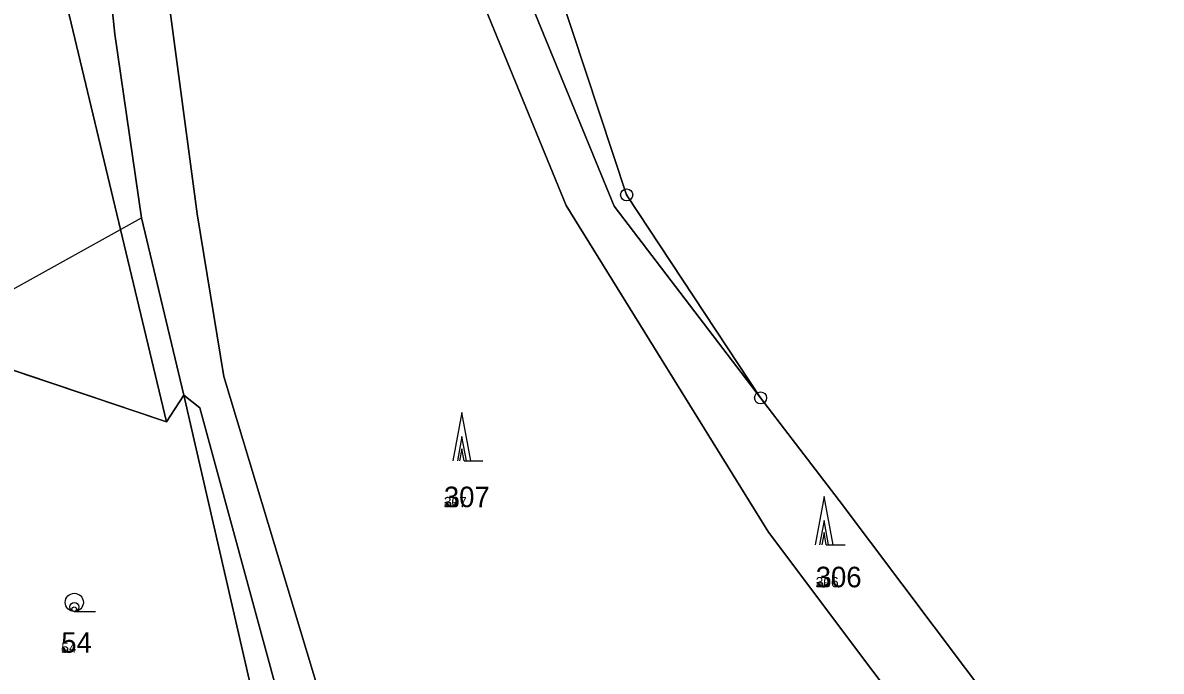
# Model space of a CAD drawing. Extents: x -759873 to -758487, y -975024 to -973516.
# Drawn here: x -759094.4 to -759000.3, y -974260.8 to -974207.1 of the extents above; entities that cross this region are included whole.
import ezdxf

# ---------------------------------------------------------------- set-up
doc = ezdxf.new("R2010")
doc.units = 0
for name, color, linetype in [('KAT_02_hranice parcel', 7, 'Continuous'), ('KAT_03_1000_čísla parcelní', 7, 'Continuous'), ('KAT_03_250_čísla parcelní', 7, 'Continuous'), ('KAT_03_500_čísla parcelní', 7, 'Continuous'), ('KAT_04_vnitřní kresba', 7, 'Continuous'), ('KAT_05_1000_značky kultur', 7, 'Continuous'), ('KAT_05_250_značky kultur', 7, 'Continuous'), ('KAT_05_500_značky kultur', 7, 'Continuous'), ('KAT_11_značky bodu BP', 7, 'Continuous'), ('KAT_14_plocha_pozemek', 7, 'Continuous')]:
    doc.layers.add(name, color=color, linetype=linetype)

msp = doc.modelspace()

# ---------------------------------------------------------------- linework, layer by layer
at = {"layer": 'KAT_02_hranice parcel'}
for p, q in [((-759082.54, -974240.13), (-759102.76, -974233.33)), ((-759081.12, -974237.92), (-759082.54, -974240.13)), ((-759072.72, -974274.42), (-759081.12, -974237.92))]:
    msp.add_line(p, q, dxfattribs=at)
for points in [[(-759057.23, -974110.82), (-759070.93, -974124.94), (-759074.88, -974130.5), (-759080.81, -974167.04), (-759083.49, -974196.85), (-759080.01, -974222.92), (-759077.81, -974236.38), (-759067.25, -974271.4), (-759032.56, -974317.79)], [(-759057.23, -974110.82), (-759060.75, -974132.98), (-759061.42, -974162.34), (-759060.12, -974196.25), (-759049.48, -974222.24), (-759032.75, -974249.27), (-759006.93, -974283.66), (-759017.69, -974290.39), (-759014.33, -974293.41)], [(-759082.54, -974240.13), (-759086.34, -974224.22), (-759091.94, -974200.78), (-759089.9, -974172.96), (-759085.8, -974168.68)], [(-759081.12, -974237.92), (-759084.6, -974223.26), (-759086.81, -974208.04), (-759088.06, -974196.14), (-759087.54, -974184.43), (-759085.8, -974168.68)], [(-759033.4, -974238.15), (-759044.48, -974221.35), (-759056.91, -974183.77)], [(-759056.91, -974183.77), (-759056.12, -974196.39), (-759045.51, -974222.29), (-759033.4, -974238.15)], [(-759081.12, -974237.92), (-759079.79, -974238.96), (-759070.66, -974272.52)], [(-759033.4, -974238.15), (-759026.91, -974246.64), (-759000.81, -974281.35), (-758999.72, -974284.7), (-759014.33, -974293.41)]]:
    msp.add_lwpolyline(points, dxfattribs=at)
at = {"layer": 'KAT_04_vnitřní kresba'}
for p, q in [((-759086.34, -974224.22), (-759084.6, -974223.26)), ((-759102.76, -974233.33), (-759086.34, -974224.22))]:
    msp.add_line(p, q, dxfattribs=at)
at = {"layer": 'KAT_05_1000_značky kultur'}
for p, q in [((-759058.11, -974239.35), (-759058.86, -974243.35)), ((-759057.36, -974243.35), (-759058.11, -974239.35)), ((-759057.36, -974243.35), (-759056.364, -974243.35)), ((-759028.15, -974246.3), (-759028.9, -974250.3)), ((-759027.4, -974250.3), (-759028.15, -974246.3)), ((-759027.4, -974250.3), (-759026.404, -974250.3)), ((-759090.173, -974255.82), (-759088.423, -974255.82))]:
    msp.add_line(p, q, dxfattribs=at)
msp.add_circle((-759090.173, -974255.07), 0.75, dxfattribs=at)
at = {"layer": 'KAT_05_250_značky kultur'}
for p, q in [((-759058.11, -974242.35), (-759058.297, -974243.35)), ((-759057.922, -974243.35), (-759058.11, -974242.35)), ((-759057.922, -974243.35), (-759057.674, -974243.35)), ((-759028.15, -974249.3), (-759028.338, -974250.3)), ((-759027.963, -974250.3), (-759028.15, -974249.3)), ((-759027.963, -974250.3), (-759027.714, -974250.3)), ((-759090.178, -974255.82), (-759089.741, -974255.82))]:
    msp.add_line(p, q, dxfattribs=at)
msp.add_circle((-759090.178, -974255.632), 0.187, dxfattribs=at)
at = {"layer": 'KAT_05_500_značky kultur'}
for p, q in [((-759058.11, -974241.35), (-759058.485, -974243.35)), ((-759057.735, -974243.35), (-759058.11, -974241.35)), ((-759057.735, -974243.35), (-759057.237, -974243.35)), ((-759028.15, -974248.3), (-759028.525, -974250.3)), ((-759027.775, -974250.3), (-759028.15, -974248.3)), ((-759027.775, -974250.3), (-759027.277, -974250.3)), ((-759090.177, -974255.82), (-759089.302, -974255.82))]:
    msp.add_line(p, q, dxfattribs=at)
msp.add_circle((-759090.176, -974255.445), 0.375, dxfattribs=at)
at = {"layer": 'KAT_11_značky bodu BP'}
for centre, radius in [((-759044.48, -974221.35), 0.5), ((-759044.48, -974221.35), 0.0303), ((-759033.4, -974238.15), 0.5), ((-759033.4, -974238.15), 0.0303)]:
    msp.add_circle(centre, radius, dxfattribs=at)
at = {"layer": 'KAT_14_plocha_pozemek'}
for points in [[(-759208.98, -974220.98), (-759187.17, -974223.14), (-759179.86, -974223.86), (-759152.65, -974224.82), (-759152.43, -974225.07), (-759148.36, -974224.76), (-759133.61, -974225.4), (-759129.65, -974225.67), (-759118.11, -974227.12), (-759102.76, -974233.33), (-759082.54, -974240.13), (-759086.34, -974224.22), (-759091.94, -974200.78), (-759089.9, -974172.96), (-759085.8, -974168.68), (-759080.44, -974126.48), (-759059.17, -974102.77), (-759054.16, -974081.34), (-759050.16, -974065.96), (-759040.87, -974035.88)], [(-758984.12, -974076.91), (-759010.79, -974116.64), (-759007.07, -974119.22), (-759009.9, -974123.16), (-759045.17, -974103.85), (-759057.23, -974110.82), (-759057.79, -974134.47), (-759058.26, -974162.28), (-759056.91, -974183.77), (-759044.48, -974221.35), (-759033.4, -974238.15), (-759026.91, -974246.64), (-759000.81, -974281.35), (-758999.72, -974284.7), (-759014.33, -974293.41), (-758997.18, -974304.01)], [(-759088.06, -974196.14), (-759086.81, -974208.04), (-759084.6, -974223.26), (-759081.12, -974237.92), (-759079.79, -974238.96), (-759070.66, -974272.52), (-759048.01, -974306.32), (-759035.84, -974324.49), (-759036.24, -974328.76), (-759037.74, -974344.49), (-759041.4, -974353.16), (-759035.22, -974352.69), (-759034.31, -974346.71), (-759033.62, -974342.2), (-759031.96, -974331.33), (-759032.33, -974323.02), (-759032.56, -974317.79), (-759067.25, -974271.4), (-759077.81, -974236.38), (-759080.01, -974222.92), (-759083.49, -974196.85)]]:
    msp.add_lwpolyline(points, dxfattribs=at)
for points in [[(-759077.81, -974236.38), (-759067.25, -974271.4), (-759032.56, -974317.79), (-759025.5, -974306.76), (-759014.33, -974293.41), (-759017.69, -974290.39), (-759006.93, -974283.66), (-759032.75, -974249.27), (-759049.48, -974222.24), (-759060.12, -974196.25), (-759061.42, -974162.34), (-759060.75, -974132.98), (-759057.23, -974110.82), (-759070.93, -974124.94), (-759074.88, -974130.5), (-759080.81, -974167.04), (-759083.49, -974196.85), (-759080.01, -974222.92)], [(-759060.12, -974196.25), (-759049.48, -974222.24), (-759032.75, -974249.27), (-759006.93, -974283.66), (-759017.69, -974290.39), (-759014.33, -974293.41), (-758999.72, -974284.7), (-759000.81, -974281.35), (-759026.91, -974246.64), (-759033.4, -974238.15), (-759045.51, -974222.29), (-759056.12, -974196.39), (-759056.91, -974183.77), (-759058.26, -974162.28), (-759057.79, -974134.47), (-759057.23, -974110.82), (-759060.75, -974132.98), (-759061.42, -974162.34)], [(-759086.81, -974208.04), (-759088.06, -974196.14), (-759087.54, -974184.43), (-759085.8, -974168.68), (-759089.9, -974172.96), (-759091.94, -974200.78), (-759086.34, -974224.22), (-759082.54, -974240.13), (-759081.12, -974237.92), (-759084.6, -974223.26)], [(-759045.51, -974222.29), (-759033.4, -974238.15), (-759044.48, -974221.35), (-759056.91, -974183.77), (-759056.12, -974196.39)], [(-759072.72, -974274.42), (-759081.12, -974237.92), (-759082.54, -974240.13), (-759102.76, -974233.33), (-759134.45, -974270.58), (-759130.63, -974274.73), (-759123.38, -974266.06), (-759120.2, -974262.27), (-759091.19, -974289.59)], [(-759070.66, -974272.52), (-759079.79, -974238.96), (-759081.12, -974237.92), (-759072.72, -974274.42)]]:
    msp.add_lwpolyline(points, close=True, dxfattribs=at)

# ---------------------------------------------------------------- texts
at = {"layer": 'KAT_03_1000_čísla parcelní'}
for s, p in [('307', (-759059.6, -974247.19)), ('306', (-759028.84, -974253.82)), ('54', (-759091.25, -974259.24))]:
    msp.add_text(s, height=1.7, dxfattribs=at).set_placement(p)
at = {"layer": 'KAT_03_250_čísla parcelní'}
for s, p in [('307', (-759059.6, -974247.19)), ('306', (-759028.84, -974253.82)), ('54', (-759091.25, -974259.24))]:
    msp.add_text(s, height=0.425, dxfattribs=at).set_placement(p)
at = {"layer": 'KAT_03_500_čísla parcelní'}
for s, p in [('307', (-759059.6, -974247.19)), ('306', (-759028.84, -974253.82)), ('54', (-759091.25, -974259.24))]:
    msp.add_text(s, height=0.85, dxfattribs=at).set_placement(p)

doc.saveas('drawing.dxf')
